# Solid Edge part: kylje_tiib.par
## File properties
Author: Georg
Template: Iso Part.par
Last saved by: Georg
Revision: 2
Application: Solid Edge
Accuracy: 0,990
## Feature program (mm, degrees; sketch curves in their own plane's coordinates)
sketch for "unnamed Protrusion 1" plane through (0, 0, 0) normal (1, 0, 0) x-axis (0, 1, 0)
  line (-7.5, -7.5) -> (7.5, -7.5)
  line (7.5, -7.5) -> (7.5, 7.5)
  line (7.5, 7.5) -> (-7.5, 7.5)
  line (-7.5, 7.5) -> (-7.5, -7.5)
  dimension (linear) = 7.5
  dimension (linear) = 7.5
extrude "unnamed Protrusion 1" add finite 55 along +normal
sketch for "ExtrudedCutout_1" plane through (55, 0, 0) normal (1, 0, 0) x-axis (0, 1, 0)
  line (-7.5042, -5) -> (2.4958, -5)
  line (2.4958, -5) -> (2.4958, 5)
  line (2.4958, 5) -> (-7.5042, 5)
  line (-7.5042, 5) -> (-7.5042, -5)
  dimension (linear) = 2.4958
  dimension (linear) = 2.4958
extrude "ExtrudedCutout_1" cut finite 66.4819 along -normal
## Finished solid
Body 1: solid body, 10 faces, 24 edges, 16 vertices.
  Faces by surface: plane 10
  Edges by curve: line 24
Bounding box of the edges (mm): 55.000 x 15.000 x 15.000, from (0, -7.5, -7.5) to (55, 7.5, 7.5).
Planar faces by outward normal: +x 1, +y 1, +z 2, -x 1, -y 3, -z 2
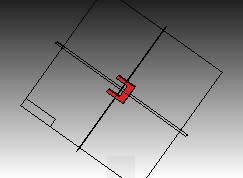
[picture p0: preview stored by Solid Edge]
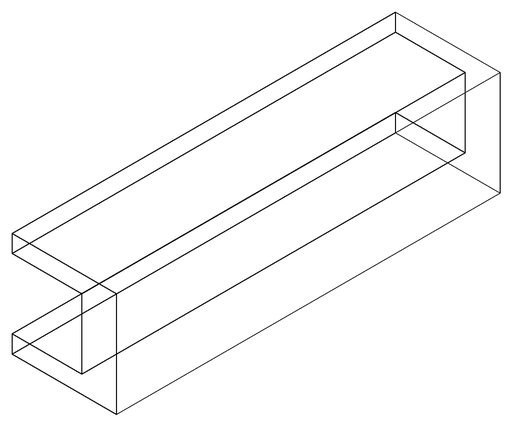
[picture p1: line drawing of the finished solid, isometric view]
